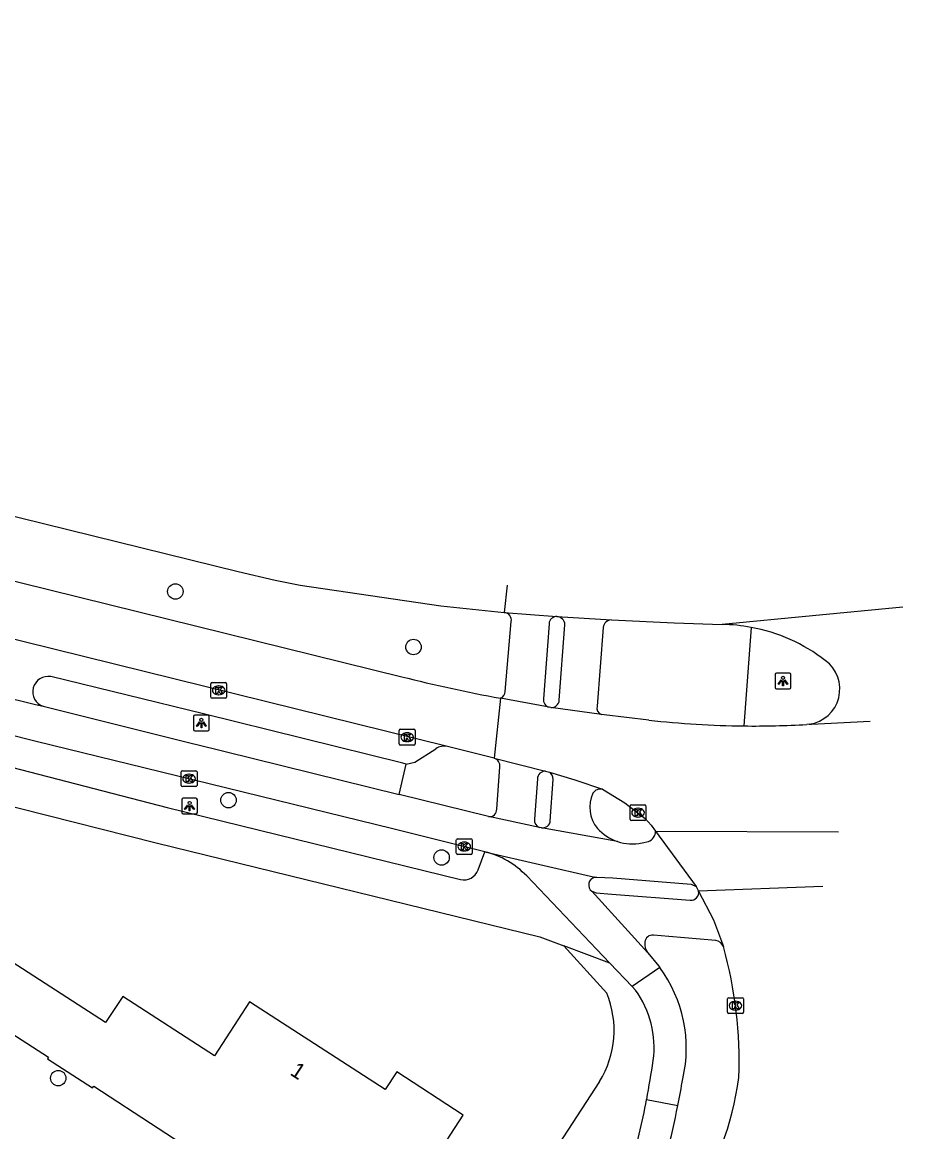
# Model space of a CAD drawing. Extents: x 161141 to 161601, y 381708 to 382245.
# Drawn here: x 161544.8 to 161600.6, y 382126.6 to 382197 of the extents above; entities that cross this region are included whole.
import ezdxf

# ---------------------------------------------------------------- set-up
doc = ezdxf.new("R2010")
doc.units = 0
for name, color, linetype in [('IMGEO_Berm_groen', 7, 'Continuous'), ('IMGEO_Boom', 7, 'Continuous'), ('IMGEO_Fietspad_gesloten', 7, 'Continuous'), ('IMGEO_Fietspad_open', 7, 'Continuous'), ('IMGEO_Kolk', 7, 'Continuous'), ('IMGEO_Lichtpunt', 7, 'Continuous'), ('IMGEO_Pand', 7, 'Continuous'), ('IMGEO_Pand_nummerreeks', 7, 'Continuous'), ('IMGEO_Parkeervlak_open', 7, 'Continuous'), ('IMGEO_Rijbaan_lokaal_gesloten', 7, 'Continuous'), ('IMGEO_Verkeerseiland_open', 7, 'Continuous'), ('IMGEO_Voetpad_open', 7, 'Continuous')]:
    doc.layers.add(name, color=color, linetype=linetype)

msp = doc.modelspace()

# ---------------------------------------------------------------- linework, layer by layer
at = {"layer": 'IMGEO_Berm_groen'}
msp.add_lwpolyline([(161568.691, 382147.976), (161569.142, 382149.901)], dxfattribs=at)
at = {"layer": 'IMGEO_Boom'}
for centre in [(161554.506, 382160.85), (161569.602, 382157.328), (161557.878, 382147.612), (161571.386, 382143.975), (161547.078, 382129.981)]:
    msp.add_circle(centre, 0.489, dxfattribs=at)
at = {"layer": 'IMGEO_Fietspad_gesloten'}
for points in [[(161531.581, 382157.18), (161538.79, 382155.377), (161545.639, 382153.688), (161546.127, 382153.566)], [(161546.127, 382153.566), (161555.682, 382151.185), (161555.792, 382151.158), (161568.691, 382147.976)], [(161574.138, 382144.342), (161568.305, 382145.8), (161553.532, 382149.4), (161545.675, 382151.345), (161543.747, 382151.827)], [(161574.358, 382146.578), (161568.691, 382147.976)], [(161577.59, 382145.885), (161574.358, 382146.578)], [(161577.725, 382145.856), (161577.59, 382145.885)], [(161582.536, 382144.993), (161577.725, 382145.856)], [(161584.097, 382144.904), (161584.497, 382145)], [(161574.138, 382144.342), (161581.108, 382142.72)], [(161582.049, 382137.272), (161581.211, 382138.152), (161576.782, 382142.804)], [(161581.108, 382142.72), (161581.172, 382142.729), (161581.235, 382142.73), (161582.249, 382142.688), (161587.211, 382142.279), (161587.528, 382142.145)], [(161584.473, 382137.935), (161580.917, 382141.83)], [(161584.473, 382137.935), (161585.156, 382137.082), (161585.226, 382136.989)], [(161583.462, 382135.788), (161582.049, 382137.272)], [(161585.226, 382136.989), (161583.462, 382135.788)]]:
    msp.add_lwpolyline(points, dxfattribs=at)
for centre, radius, start, end in [((161584.299, 382145.617), 0.648, 287.8168, 3.24055), ((161583.478, 382147.782), 2.944, 251.33685, 282.13681), ((161572.854, 382139.092), 5.405, 43.37531, 76.25204), ((161581.21, 382142.233), 0.498, 101.79945, 233.97587)]:
    msp.add_arc(centre, radius, start, end, dxfattribs=at)
at = {"layer": 'IMGEO_Fietspad_open'}
for points in [[(161578.852, 382153.946), (161579.207, 382158.739)], [(161581.635, 382158.565), (161581.248, 382153.571)], [(161578.281, 382146.309), (161578.46, 382148.932)], [(161583.673, 382135.566), (161583.462, 382135.788)]]:
    msp.add_lwpolyline(points, dxfattribs=at)
for centre, radius, start, end in [((161578.658, 382158.718), 0.549, 2.16842, 85.84081), ((161582.159, 382158.52), 0.526, 89.80555, 175.07708), ((161578.359, 382153.99), 0.495, 265.84922, 354.92386), ((161581.662, 382153.457), 0.429, 164.6063, 250.96526), ((161577.962, 382148.953), 0.498, 357.58955, 58.9662), ((161582.897, 382147.169), 2.113, 155.33774, 219.50747), ((161581.454, 382147.759), 0.559, 75.70383, 148.54005), ((161577.78, 382146.356), 0.503, 263.68363, 354.65909), ((161583.464, 382147.792), 2.948, 221.83779, 251.66176), ((161578.308, 382131.886), 8.597, 346.92677, 36.41756), ((161578.756, 382131.948), 6.105, 351.98585, 36.34593), ((161535.775, 382138.001), 49.51, 349.09095, 351.98441), ((161525.846, 382140.271), 61.707, 348.75466, 350.36354)]:
    msp.add_arc(centre, radius, start, end, dxfattribs=at)
at = {"layer": 'IMGEO_Kolk'}
for p, q in [((161556.755, 382154.15), (161556.755, 382155.002)), ((161556.83, 382155.076), (161557.682, 382155.076)), ((161557.243, 382154.856), (161557.268, 382154.856)), ((161557.756, 382155.002), (161557.756, 382154.15)), ((161557.682, 382154.076), (161556.83, 382154.076)), ((161557.266, 382154.296), (161557.241, 382154.296)), ((161568.705, 382151.181), (161568.705, 382152.033)), ((161568.78, 382152.107), (161569.632, 382152.107)), ((161569.193, 382151.887), (161569.218, 382151.887)), ((161569.706, 382152.033), (161569.706, 382151.181)), ((161569.216, 382151.327), (161569.191, 382151.327)), ((161569.632, 382151.107), (161568.78, 382151.107)), ((161554.877, 382148.548), (161554.877, 382149.4)), ((161554.952, 382149.474), (161555.804, 382149.474)), ((161555.365, 382149.254), (161555.39, 382149.254)), ((161555.878, 382149.4), (161555.878, 382148.548)), ((161555.804, 382148.474), (161554.952, 382148.474)), ((161555.388, 382148.694), (161555.363, 382148.694)), ((161583.346, 382146.397), (161583.346, 382147.249)), ((161583.421, 382147.323), (161584.273, 382147.323)), ((161583.834, 382147.103), (161583.859, 382147.103)), ((161584.347, 382147.249), (161584.347, 382146.397)), ((161584.273, 382146.323), (161583.421, 382146.323)), ((161583.857, 382146.543), (161583.832, 382146.543)), ((161572.321, 382144.244), (161572.321, 382145.096)), ((161572.396, 382145.17), (161573.248, 382145.17)), ((161572.809, 382144.95), (161572.834, 382144.95)), ((161573.322, 382145.096), (161573.322, 382144.244)), ((161573.248, 382144.17), (161572.396, 382144.17)), ((161572.832, 382144.39), (161572.807, 382144.39)), ((161589.521, 382134.155), (161589.521, 382135.007)), ((161589.596, 382135.081), (161590.448, 382135.081)), ((161590.522, 382135.007), (161590.522, 382134.155)), ((161590.032, 382134.301), (161590.007, 382134.301)), ((161590.009, 382134.861), (161590.034, 382134.861)), ((161590.448, 382134.081), (161589.596, 382134.081))]:
    msp.add_line(p, q, dxfattribs=at)
for points in [[(161556.755, 382154.15), (161556.755, 382155.002)], [(161556.83, 382155.076), (161557.682, 382155.076)], [(161557.076, 382154.776), (161557.199, 382154.776), (161557.199, 382154.625), (161557.329, 382154.776), (161557.493, 382154.776), (161557.347, 382154.625), (161557.5, 382154.376), (161557.348, 382154.376), (161557.263, 382154.54), (161557.199, 382154.473), (161557.199, 382154.376), (161557.076, 382154.376), (161557.076, 382154.776)], [(161557.756, 382155.002), (161557.756, 382154.15)], [(161557.682, 382154.076), (161556.83, 382154.076)], [(161568.705, 382151.181), (161568.705, 382152.033)], [(161568.78, 382152.107), (161569.632, 382152.107)], [(161569.706, 382152.033), (161569.706, 382151.181)], [(161569.026, 382151.807), (161569.149, 382151.807), (161569.149, 382151.656), (161569.279, 382151.807), (161569.443, 382151.807), (161569.297, 382151.656), (161569.45, 382151.407), (161569.298, 382151.407), (161569.213, 382151.571), (161569.149, 382151.504), (161569.149, 382151.407), (161569.026, 382151.407), (161569.026, 382151.807)], [(161569.632, 382151.107), (161568.78, 382151.107)], [(161554.877, 382148.548), (161554.877, 382149.4)], [(161554.952, 382149.474), (161555.804, 382149.474)], [(161555.198, 382149.174), (161555.321, 382149.174), (161555.321, 382149.023), (161555.451, 382149.174), (161555.615, 382149.174), (161555.469, 382149.023), (161555.622, 382148.774), (161555.47, 382148.774), (161555.385, 382148.938), (161555.321, 382148.871), (161555.321, 382148.774), (161555.198, 382148.774), (161555.198, 382149.174)], [(161555.878, 382149.4), (161555.878, 382148.548)], [(161555.804, 382148.474), (161554.952, 382148.474)], [(161583.346, 382146.397), (161583.346, 382147.249)], [(161583.421, 382147.323), (161584.273, 382147.323)], [(161583.667, 382147.023), (161583.79, 382147.023), (161583.79, 382146.872), (161583.92, 382147.023), (161584.084, 382147.023), (161583.938, 382146.872), (161584.091, 382146.623), (161583.939, 382146.623), (161583.854, 382146.787), (161583.79, 382146.72), (161583.79, 382146.623), (161583.667, 382146.623), (161583.667, 382147.023)], [(161584.347, 382147.249), (161584.347, 382146.397)], [(161584.273, 382146.323), (161583.421, 382146.323)], [(161572.321, 382144.244), (161572.321, 382145.096)], [(161572.396, 382145.17), (161573.248, 382145.17)], [(161572.642, 382144.87), (161572.765, 382144.87), (161572.765, 382144.719), (161572.895, 382144.87), (161573.059, 382144.87), (161572.913, 382144.719), (161573.066, 382144.47), (161572.914, 382144.47), (161572.829, 382144.634), (161572.765, 382144.567), (161572.765, 382144.47), (161572.642, 382144.47), (161572.642, 382144.87)], [(161573.322, 382145.096), (161573.322, 382144.244)], [(161573.248, 382144.17), (161572.396, 382144.17)], [(161589.521, 382134.155), (161589.521, 382135.007)], [(161589.596, 382135.081), (161590.448, 382135.081)], [(161590.522, 382135.007), (161590.522, 382134.155)], [(161589.842, 382134.781), (161589.965, 382134.781), (161589.965, 382134.63), (161590.095, 382134.781), (161590.259, 382134.781), (161590.113, 382134.63), (161590.266, 382134.381), (161590.114, 382134.381), (161590.029, 382134.545), (161589.965, 382134.478), (161589.965, 382134.381), (161589.842, 382134.381), (161589.842, 382134.781)], [(161590.448, 382134.081), (161589.596, 382134.081)]]:
    msp.add_lwpolyline(points, dxfattribs=at)
for centre, start, end in [((161556.832, 382155), 91.55205, 178.44795), ((161556.832, 382155), 91.55205, 178.44795), ((161557.68, 382155), 1.55205, 88.44795), ((161557.68, 382155), 1.55205, 88.44795), ((161556.832, 382154.152), 181.55205, 268.44795), ((161556.832, 382154.152), 181.55205, 268.44795), ((161557.68, 382154.152), 271.55205, 358.44795), ((161557.68, 382154.152), 271.55205, 358.44795), ((161568.782, 382152.031), 91.55205, 178.44795), ((161568.782, 382152.031), 91.55205, 178.44795), ((161569.63, 382152.031), 1.55205, 88.44795), ((161569.63, 382152.031), 1.55205, 88.44795), ((161568.782, 382151.183), 181.55205, 268.44795), ((161568.782, 382151.183), 181.55205, 268.44795), ((161569.63, 382151.183), 271.55205, 358.44795), ((161569.63, 382151.183), 271.55205, 358.44795), ((161554.954, 382149.398), 91.55205, 178.44795), ((161554.954, 382149.398), 91.55205, 178.44795), ((161555.802, 382149.398), 1.55205, 88.44795), ((161555.802, 382149.398), 1.55205, 88.44795), ((161554.954, 382148.55), 181.55205, 268.44795), ((161554.954, 382148.55), 181.55205, 268.44795), ((161555.802, 382148.55), 271.55205, 358.44795), ((161555.802, 382148.55), 271.55205, 358.44795), ((161583.423, 382147.247), 91.55205, 178.44795), ((161583.423, 382147.247), 91.55205, 178.44795), ((161584.271, 382147.247), 1.55205, 88.44795), ((161584.271, 382147.247), 1.55205, 88.44795), ((161583.423, 382146.399), 181.55205, 268.44795), ((161583.423, 382146.399), 181.55205, 268.44795), ((161584.271, 382146.399), 271.55205, 358.44795), ((161584.271, 382146.399), 271.55205, 358.44795), ((161572.398, 382145.094), 91.55205, 178.44795), ((161572.398, 382145.094), 91.55205, 178.44795), ((161573.246, 382145.094), 1.55205, 88.44795), ((161573.246, 382145.094), 1.55205, 88.44795), ((161572.398, 382144.246), 181.55205, 268.44795), ((161572.398, 382144.246), 181.55205, 268.44795), ((161573.246, 382144.246), 271.55205, 358.44795), ((161573.246, 382144.246), 271.55205, 358.44795), ((161589.598, 382135.005), 91.55205, 178.44795), ((161589.598, 382135.005), 91.55205, 178.44795), ((161590.446, 382135.005), 1.55205, 88.44795), ((161590.446, 382135.005), 1.55205, 88.44795), ((161589.598, 382134.157), 181.55205, 268.44795), ((161589.598, 382134.157), 181.55205, 268.44795), ((161590.446, 382134.157), 271.55205, 358.44795), ((161590.446, 382134.157), 271.55205, 358.44795)]:
    msp.add_arc(centre, 0.0765, start, end, dxfattribs=at)
for centre, major_axis, ratio, start_param, end_param in [((161557.242, 382154.576), (-0.387, 0.002), 0.722429, 4.712389, 7.853982), ((161557.267, 382154.576), (-0.39, 0.002), 0.717154, 1.570796, 4.712389), ((161569.192, 382151.607), (-0.387, 0.002), 0.722429, 4.712389, 7.853982), ((161569.217, 382151.607), (-0.39, 0.002), 0.717154, 1.570796, 4.712389), ((161555.364, 382148.974), (-0.387, 0.002), 0.722429, 4.712389, 7.853982), ((161555.389, 382148.974), (-0.39, 0.002), 0.717154, 1.570796, 4.712389), ((161583.833, 382146.823), (-0.387, 0.002), 0.722429, 4.712389, 7.853982), ((161583.858, 382146.823), (-0.39, 0.002), 0.717154, 1.570796, 4.712389), ((161572.808, 382144.67), (-0.387, 0.002), 0.722429, 4.712389, 7.853982), ((161572.833, 382144.67), (-0.39, 0.002), 0.717154, 1.570796, 4.712389), ((161590.008, 382134.581), (-0.387, 0.002), 0.722429, 4.712389, 7.853982), ((161590.033, 382134.581), (-0.39, 0.002), 0.717154, 1.570796, 4.712389)]:
    msp.add_ellipse(centre, major_axis=major_axis, ratio=ratio, start_param=start_param, end_param=end_param, dxfattribs=at)
at = {"layer": 'IMGEO_Lichtpunt'}
for p, q in [((161592.535, 382155.576), (161592.535, 382154.769)), ((161592.535, 382155.576), (161592.535, 382154.769)), ((161593.437, 382155.671), (161592.629, 382155.671)), ((161593.437, 382155.671), (161592.629, 382155.671)), ((161593.531, 382154.769), (161593.531, 382155.576)), ((161593.531, 382154.769), (161593.531, 382155.576)), ((161592.629, 382154.675), (161593.437, 382154.675)), ((161592.629, 382154.675), (161593.437, 382154.675)), ((161555.656, 382152.912), (161555.656, 382152.105)), ((161555.656, 382152.912), (161555.656, 382152.105)), ((161556.558, 382153.007), (161555.75, 382153.007)), ((161556.558, 382153.007), (161555.75, 382153.007)), ((161556.652, 382152.105), (161556.652, 382152.912)), ((161556.652, 382152.105), (161556.652, 382152.912)), ((161555.75, 382152.011), (161556.558, 382152.011)), ((161555.75, 382152.011), (161556.558, 382152.011)), ((161555.81, 382147.735), (161555.002, 382147.735)), ((161555.81, 382147.735), (161555.002, 382147.735)), ((161554.908, 382147.64), (161554.908, 382146.833)), ((161554.908, 382147.64), (161554.908, 382146.833)), ((161555.904, 382146.833), (161555.904, 382147.64)), ((161555.904, 382146.833), (161555.904, 382147.64)), ((161555.002, 382146.739), (161555.81, 382146.739)), ((161555.002, 382146.739), (161555.81, 382146.739))]:
    msp.add_line(p, q, dxfattribs=at)
for points in [[(161592.909, 382155.24), (161592.948, 382155.212), (161592.76, 382154.95), (161592.722, 382154.977), (161592.909, 382155.24)], [(161593.011, 382155.192), (161593.058, 382155.192), (161593.058, 382154.87), (161593.011, 382154.87), (161593.011, 382155.192)], [(161593.121, 382155.212), (161593.159, 382155.239), (161593.346, 382154.977), (161593.307, 382154.949), (161593.121, 382155.212)], [(161556.03, 382152.576), (161556.069, 382152.548), (161555.881, 382152.286), (161555.843, 382152.313), (161556.03, 382152.576)], [(161556.242, 382152.548), (161556.28, 382152.575), (161556.467, 382152.313), (161556.428, 382152.285), (161556.242, 382152.548)], [(161556.132, 382152.528), (161556.179, 382152.528), (161556.179, 382152.206), (161556.132, 382152.206), (161556.132, 382152.528)], [(161555.282, 382147.304), (161555.321, 382147.276), (161555.133, 382147.014), (161555.095, 382147.041), (161555.282, 382147.304)], [(161555.384, 382147.256), (161555.431, 382147.256), (161555.431, 382146.934), (161555.384, 382146.934), (161555.384, 382147.256)], [(161555.494, 382147.276), (161555.532, 382147.303), (161555.719, 382147.041), (161555.68, 382147.013), (161555.494, 382147.276)]]:
    msp.add_lwpolyline(points, dxfattribs=at)
for centre in [(161593.034, 382155.374), (161556.155, 382152.71), (161555.407, 382147.438)]:
    msp.add_circle(centre, 0.0994, dxfattribs=at)
for centre, start, end in [((161592.629, 382155.576), 90, 180), ((161592.629, 382155.576), 90, 180), ((161593.437, 382155.576), 0, 90), ((161593.437, 382155.576), 0, 90), ((161592.629, 382154.769), 180, 270), ((161592.629, 382154.769), 180, 270), ((161593.437, 382154.769), 270, 0), ((161593.437, 382154.769), 270, 360), ((161555.75, 382152.912), 90, 180), ((161555.75, 382152.912), 90, 180), ((161556.558, 382152.912), 0, 90), ((161556.558, 382152.912), 0, 90), ((161555.75, 382152.105), 180, 270), ((161555.75, 382152.105), 180, 270), ((161556.558, 382152.105), 270, 0), ((161556.558, 382152.105), 270, 360), ((161555.002, 382147.64), 90, 180), ((161555.002, 382147.64), 90, 180), ((161555.81, 382147.64), 0, 90), ((161555.81, 382147.64), 0, 90), ((161555.002, 382146.833), 180, 270), ((161555.002, 382146.833), 180, 270), ((161555.81, 382146.833), 270, 0), ((161555.81, 382146.833), 270, 360)]:
    msp.add_arc(centre, 0.0946, start, end, dxfattribs=at)
at = {"layer": 'IMGEO_Pand'}
for points in [[(161550.072, 382133.499), (161541.319, 382139.15), (161537.458, 382133.165), (161541.046, 382130.85), (161542.779, 382133.537), (161543.353, 382133.166), (161543.421, 382133.271), (161546.466, 382131.307), (161546.398, 382131.202), (161549.259, 382129.356), (161549.327, 382129.461), (161561.573, 382121.485)], [(161567.013, 382118.771), (161572.764, 382127.628), (161568.543, 382130.38), (161567.811, 382129.265), (161559.207, 382134.83), (161556.993, 382131.385), (161551.185, 382135.157), (161550.072, 382133.499)]]:
    msp.add_lwpolyline(points, dxfattribs=at)
at = {"layer": 'IMGEO_Parkeervlak_open'}
for points in [[(161569.142, 382149.901), (161568.93, 382149.958), (161556.292, 382153.08), (161546.612, 382155.453)], [(161569.142, 382149.901), (161569.692, 382150.02), (161571.016, 382150.879)]]:
    msp.add_lwpolyline(points, dxfattribs=at)
for centre, radius, start, end in [((161546.444, 382154.49), 0.977, 80.08882, 251.08265), ((161571.568, 382150.009), 1.03, 78.61773, 122.3924)]:
    msp.add_arc(centre, radius, start, end, dxfattribs=at)
at = {"layer": 'IMGEO_Rijbaan_lokaal_gesloten'}
for points in [[(161417.456, 382196.964), (161420.058, 382196.306), (161460.894, 382186.197), (161500, 382176.547), (161558.491, 382162.113), (161560.838, 382161.565), (161562.428, 382161.253), (161571.347, 382159.936), (161575.364, 382159.517)], [(161416.542, 382193.184), (161418.72, 382192.635), (161459.898, 382182.379), (161500, 382172.465), (161568.862, 382155.44)], [(161571.771, 382151.019), (161502.587, 382168.125), (161500, 382168.766), (161459.102, 382178.908), (161420.449, 382188.487), (161415.442, 382189.785), (161412.878, 382190.505)], [(161575.538, 382161.247), (161575.364, 382159.517)], [(161600.631, 382159.85), (161600.631, 382159.85), (161589.173, 382158.758)], [(161575.364, 382159.517), (161578.698, 382159.266)], [(161578.698, 382159.266), (161582.161, 382159.046)], [(161582.161, 382159.046), (161586.144, 382158.862), (161589.173, 382158.758)], [(161575.117, 382154.078), (161574.719, 382150.267)], [(161578.216, 382153.513), (161575.117, 382154.078)], [(161578.323, 382153.496), (161578.216, 382153.513)], [(161581.522, 382153.051), (161578.323, 382153.496)], [(161584.529, 382152.691), (161581.689, 382153.028), (161581.522, 382153.051)], [(161594.703, 382152.43), (161594.851, 382152.437), (161598.566, 382152.621)], [(161594.703, 382152.43), (161594.552, 382152.413)], [(161574.719, 382150.267), (161571.771, 382151.019)], [(161574.719, 382150.267), (161577.978, 382149.452)], [(161577.978, 382149.452), (161578.219, 382149.38)], [(161578.219, 382149.38), (161579.826, 382148.903), (161581.592, 382148.301)], [(161581.592, 382148.301), (161583.013, 382147.446), (161584.296, 382146.447), (161584.666, 382146.035), (161584.946, 382145.654)], [(161584.946, 382145.654), (161587.528, 382142.145)], [(161584.946, 382145.654), (161596.564, 382145.611)], [(161587.528, 382142.145), (161587.686, 382141.844)], [(161595.571, 382142.135), (161587.686, 382141.844)], [(161587.686, 382141.844), (161588.619, 382140.029), (161589.261, 382138.322)], [(161584.39, 382128.631), (161586.368, 382128.237)]]:
    msp.add_lwpolyline(points, dxfattribs=at)
for centre, radius, start, end in [((161589.01, 382147.79), 10.969, 79.45612, 89.1473), ((161589, 382147.738), 11.022, 52.46296, 79.45829), ((161594.383, 382154.661), 2.254, 278.17467, 53.7262), ((161592.831, 382250.474), 98.01, 255.84435, 259.58731), ((161591.141, 382211.123), 58.805, 263.54372, 269.42678), ((161591.2, 382211.155), 58.838, 269.36992, 273.26588), ((161562.897, 382131.03), 27.354, 357.86961, 15.46124), ((161571.45, 382132.448), 18.939, 325.53522, 352.61152), ((161536.078, 382137.935), 49.199, 343.83692, 349.09958), ((161526.101, 382140.245), 61.452, 342.92824, 348.73123)]:
    msp.add_arc(centre, radius, start, end, dxfattribs=at)
at = {"layer": 'IMGEO_Verkeerseiland_open'}
msp.add_lwpolyline([(161591.017, 382158.574), (161590.553, 382152.321)], dxfattribs=at)
at = {"layer": 'IMGEO_Voetpad_open'}
for points in [[(161387.058, 382185.651), (161389.844, 382185.251), (161418.52, 382178.097), (161457.897, 382168.303), (161477.956, 382163.494), (161500, 382158.072), (161544.61, 382147.101), (161553.295, 382144.911), (161577.621, 382138.939), (161579.137, 382138.37)], [(161575.423, 382154.516), (161575.807, 382158.946)], [(161578.2, 382158.809), (161577.851, 382154.046)], [(161544.121, 382149.704), (161553.984, 382147.153), (161572.587, 382142.588)], [(161574.88, 382147.043), (161575.088, 382149.718)], [(161577.462, 382148.962), (161577.269, 382146.408)], [(161573.699, 382143.186), (161574.138, 382144.342)], [(161580.917, 382141.83), (161581.181, 382141.736), (161582.179, 382141.649), (161587.152, 382141.261)], [(161588.781, 382138.72), (161585.793, 382138.955), (161584.828, 382139.056)], [(161582.049, 382137.272), (161579.137, 382138.37)], [(161579.137, 382138.37), (161581.865, 382135.377)], [(161581.409, 382129.761), (161561.628, 382099.383), (161523.437, 382040.853)]]:
    msp.add_lwpolyline(points, dxfattribs=at)
for centre, radius, start, end in [((161575.324, 382159.028), 0.49, 350.32513, 85.28576), ((161578.702, 382158.761), 0.505, 90.5022, 174.58118), ((161574.946, 382154.523), 0.477, 290.99608, 359.1253), ((161578.324, 382153.978), 0.478, 171.84579, 256.96113), ((161574.574, 382149.771), 0.517, 354.12182, 73.69074), ((161577.961, 382148.954), 0.499, 88.00731, 179.03174), ((161574.442, 382147.009), 0.439, 258.97932, 4.41027), ((161577.762, 382146.351), 0.496, 173.36877, 249.71167), ((161572.81, 382143.505), 0.944, 256.31287, 340.22717), ((161587.182, 382141.77), 0.51, 266.65447, 8.36915), ((161585.136, 382138.501), 0.872, 173.35215, 220.50287), ((161584.778, 382138.547), 0.511, 84.42823, 173.83676), ((161588.583, 382137.993), 0.754, 25.91151, 74.75971), ((161576.087, 382133.02), 6.24, 328.51905, 22.19687)]:
    msp.add_arc(centre, radius, start, end, dxfattribs=at)

# ---------------------------------------------------------------- texts
at = {"layer": 'IMGEO_Pand_nummerreeks'}
msp.add_text('1', height=1, rotation=326.90596, dxfattribs=at).set_placement((161561.715, 382130.232))

doc.saveas('drawing.dxf')
